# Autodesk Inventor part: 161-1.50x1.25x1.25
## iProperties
Created: 2007-06
Part Number: 161-1.50x1.25x1.25
Document SubType Name: Modeling
Designer: btaylor
Density: 1 g/cm^3
Author: btaylor
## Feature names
1. Revolution1
2. Extrusion1
3. Extrusion2
4. Extrusion3
5. Extrusion4
6. Fillet1
7. Fillet2
8. Fillet3
9. Fillet4
10. Extrusion5
11. Extrusion6
12. Extrusion7
13. Revolution2
14. Extrusion8
15. Fillet5
16. Fillet6
17. Fillet7
18. Fillet8
19. Chamfer1
20. Chamfer2
21. Chamfer3
22. Fillet9
23. Fillet10
24. Fillet11
